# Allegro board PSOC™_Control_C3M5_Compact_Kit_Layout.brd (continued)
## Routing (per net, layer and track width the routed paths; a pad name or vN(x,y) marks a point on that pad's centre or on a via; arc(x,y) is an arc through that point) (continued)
XTAL1: length 8.3
  BOTTOM w0.152: Y1.1 24.86,19.77 24.64,19.55 22.44,19.55 22.25,19.74 C13.1 21.6,19.34 21.35,19.09 20.4,19.09 18.98,17.67 U2.29
XTAL2: length 3.7
  BOTTOM w0.152: R12.1 21.66,18.36 22.23,18.36 22.58,18.71 Y1.3 23.56,17.81 23.69,17.68 C14.1
N07345: length 2.6
  TOP w0.381: 6.1,8.62 J1.1 ; 8.15,7.52 8.22,7.59 FB1.1 9.82,7.59
N07349: length 4.4
  TOP w0.381: FB1.2 9.82,6.09 ; FB1.2 9.09,5.41 ; FB1.2 8.36,6.09 ; 11,6.22 D1.A 10.47,5.59 ; 9.68,4.6 C10.1 9.13,5.14
N08163: length 7.4
  TOP w0.381: v1(43.21,23.4) 43.33,23.27 v1(43.33,22.81) 43.64,22.51 43.64,21.77 v1(42.57,20.71)
  BOTTOM w0.381: L1.2 42.88,23.55 ; v1(42.57,20.71) 41.95,20.08 U5.1 ; 43.54,23.12 D2.A 44.07,23.76
N11111: length 2.5
  BOTTOM w0.229: R14.2 9.4,14.51 9.57,14.69 10.45,14.69 10.93,15.17 U2.3
N20632: length 15.1
  TOP w0.381: v1(39.9,19.79) 40.4,20.28 41.8,20.28 41.96,20.12 42.88,20.12 44.27,21.52 44.27,22.74 v1(44.93,23.4)
  BOTTOM w0.33: R4.1 45.69,24.14 45.94,23.89 46.34,23.89 46.35,23.89 47.78,23.89 R1.2
  BOTTOM w0.381: v1(39.9,19.79) 40.05,19.65 U5.3 ; C1.2 49.86,23.41 R1.2 ; v1(44.93,23.4) 44.93,24.16 45.31,24.54 R4.1
N32254: length 2.6
  BOTTOM w0.152: R12.2 20.22,18.34 19.05,17.17 U2.30
N37178: length 4
  TOP w0.203: U3.8 41.31,6.56 41.52,6.35 v1(41.53,6.35)
  BOTTOM w0.203: v1(41.53,6.35) 42.05,5.83 R18.2 43.41,5.83 43.42,5.83 43.92,5.83 C28.1
N38243: length 4.8
  TOP w0.292: U3.30 35,13.75 v1(34.9,13.64)
  BOTTOM w0.356: C25.1 37.93,13.6 37.64,13.9 35.15,13.9 v1(34.9,13.64)
N38502: length 40.2
  TOP w0.229: U3.13 47.33,8.17 ; 47.29,9.5 47.3,9.5 U3.15 ; U3.14 47.32,8.9 ; U3.12 47.26,7.57
  TOP w0.254: U3.20 47.21,18.58 ; U3.21 45.71,18.6
  TOP w0.381: U3.12 48.51,7.57 ; U3.15 48.51,9.5 ; U3.20 47.96,19 48.01,18.95 ; U3.14 48.51,8.9 ; U3.13 v1(48.51,8.17)
  TOP w0.457: v1(52.93,8.84) v1(52.93,9.48) 52.91,9.5 52.91,17.17 52.1,17.99 v1(50.98,17.99)
  BOTTOM w0.152: TIE1.1 47.85,11.92 48.31,11.46 R16.1
  BOTTOM w0.254: v1(49.43,8.18) 49.42,8.2 47.74,8.2
  BOTTOM w0.305: 47.74,8.2 47.01,7.46 47.01,5.08 46.5,4.57 45.64,4.57 45.21,4.14 41.07,4.14 40.09,5.12 R19.1
  BOTTOM w0.381: R16.1 49.12,10.04 ; R16.1 47.51,10.04 ; R16.1 48.31,8.46 ; v1(52.93,9.48) v1(52.93,8.84) 52.86,8.77 49.68,8.77 v1(49.66,8.75)
  vias: v1(49.43,10.57) v1(49.63,9.91) v1(49.64,9.33) v1(49.71,18.6) v1(49.71,17.99) v1(50.34,18.6) v1(50.34,17.99) v1(50.98,18.6)
N50220: length 8.3
  BOTTOM w0.152: R10.1 R8.1 7.21,19.06 7.5,19.06 7.68,19.23 9.5,19.23 10.57,18.17 10.57,17.56 10.95,17.17 U2.7
N86492: length 1.9
  TOP w0.152: v1(6.33,24.13) 6.05,24.41 D3.A
  BOTTOM w0.152: R7.2 6.25,24.21 v1(6.33,24.13)
N117783: length 7
  BOTTOM w0.152: R31.2 34.52,19.24 34.37,19.4 34.37,20.55 34.52,20.7 U6.3 37.03,20.7 C46.1 ; C46.1 38.28,20.67 R68.2 ; C46.1 R69.1
N117862: length 5.8
  BOTTOM w0.152: R33.2 33.91,19.24 34.06,19.4 34.06,20.55 33.91,20.7 U6.4 31.85,20.7 C50.1 30.25,21.08 R36.1
N117920: length 16.7
  TOP w0.152: R32.1 26.67,21.67 26.82,21.82 v1(27.3,21.82)
  BOTTOM w0.152: v1(27.3,21.82) 27.3,22.08 29.03,23.8 34.82,23.8 35.57,23.06 U6.1 34.66,22.6 34.12,22.06 C50.2 30.25,22.06 R36.2
N133373: length 2
  TOP w0.152: v1(14.73,24.54) 14.61,24.41 D7.K
  BOTTOM w0.152: v1(14.73,24.54) 14.96,24.31 R26.2
N133421: length 1.9
  TOP w0.152: D8.K v1(10.54,24.41)
  BOTTOM w0.152: v1(10.54,24.41) 10.46,24.33 R29.2
N143868: length 2.4
  TOP w0.152: R21.2 30.79,23.25 R20.2
N214953: length 2.4
  BOTTOM w0.152: R39.1 16.34,11.72 16.74,12.12 U2.39
N215126: length 3.3
  BOTTOM w0.152: U2.36 18.44,12.25 17.91,11.72 R40.1
N223602: length 7
  BOTTOM w0.152: R51.2 48.33,1.27 52.3,1.27 53.21,2.19 J3.9
N254765: length 19.1
  BOTTOM w0.152: R53.2 23.7,9.51 18.57,9.51 18.41,9.35 16.25,9.35 15.6,8.7 12.46,8.7 11.58,9.58 11.58,11.41 11.73,11.56 12.24,11.56 12.85,12.17 12.85,12.88 12.74,13 U2.47
N255191: length 2.1
  TOP w0.152: D9.A 5.4,22.93 v1(4.95,23.38)
  BOTTOM w0.152: R47.2 4.71,23.61 v1(4.95,23.38)
N338896: length 6.1
  TOP w0.152: D10.A 44.61,4.32 R63.2 43.16,4.75 42.77,5.14 41.86,5.14 40.66,6.33 U3.7
N367460: length 4
  BOTTOM w0.229: U2.4 10.54,15.67 10.19,15.32 8.86,15.32 R13.2
N371560: length 1.6
  TOP w0.152: R48.1 28.39,9.82 28.07,10.14 U1.10

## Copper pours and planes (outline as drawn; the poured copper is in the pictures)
15V_OUT on TOP: 36.73,10.01 35.56,10.01 35.33,9.78 35.33,8.84 35.59,8.59 36.86,8.59 36.93,8.67 36.93,9.81
15V_OUT on BOTTOM: 43.79,19.59 43.31,20.07 43.31,21.09 43.79,21.57 47.07,21.57 47.5,22 57.12,22 57.23,21.9 57.23,20.73 56.59,20.1 52.04,20.1 51.54,19.59
GND_EARTH on BOTTOM: 3.94,8.04 5.68,9.78 5.68,16.47 5.03,17.12 2.82,17.12 2.31,16.62 2.31,4.03 2.63,3.71 3.94,3.71 3.94,3.71
GND_SIGNAL on TOP: 0.76,24.73 0.95,25.09 1.33,25.23 53.72,25.24 57.57,25.24 57.81,25 57.81,23.55 57.66,23.4 53.87,23.4 53.72,23.25 53.72,12.22 52.63,12.22 52.63,8.74 53.72,8.74 53.72,0.76 1.27,0.76 0.91,0.91 0.76,1.27 0.76,6.18 2.26,6.18 2.26,19.82 0.76,19.82 ; 25 cut-outs
GND_SIGNAL on BOTTOM: 53.47,25.24 57.29,25.24 57.81,24.72 57.81,23.25 57.35,22.79 54.71,22.79 54.64,22.86 53.64,22.86 53.47,22.69 53.47,19.92 52.15,19.92 51.68,19.45 49.64,19.45 49.23,19.03 49.23,17.07 48.67,17.07 48.67,11.87 48.72,11.87 48.72,11.46 49.15,11.46 49.15,11.87 53.47,11.87 53.47,11.76 50.7,11.76 50.11,11.18 50.11,8.56 50.42,8.26 50.22,8.26 50.22,7.68 51.28,7.68 51.28,2.37 52.15,2.37 52.15,7.68 53.06,7.68 53.06,2.19 53.47,2.19 53.47,0.76 1.27,0.76 0.91,0.91 0.76,1.27 0.76,6.18 2.26,6.18 2.26,19.82 0.76,19.82 0.76,24.73 0.95,25.09 1.33,25.23 ; 13 cut-outs
VBUS on TOP: 10.26,7.32 10.44,7.14 13.72,7.14 13.89,6.96 15.21,6.96 15.39,7.14 15.39,8.36 14.33,9.43 10.54,9.43 10.26,9.15
VBUS on BOTTOM: 40.18,24.57 39.22,24.57 38.73,24.08 38.73,20.76 39.01,20.48 41.99,20.48 42.52,21.01 42.52,21.7 42.11,22.1 40.82,22.1 40.41,22.51 40.41,24.34
VBUS on BOTTOM: 17.35,4.98 15.62,4.98 15.37,5.24 15.37,6.43 16.48,7.55 17.86,7.55 17.96,7.65 17.96,8.11 17.78,8.28 14.2,8.28 13.59,7.68 13.59,4.22 14.22,3.59 17.32,3.59 17.75,4.02 17.75,4.58
VCC_3V3 on TOP: 13.91,3.16 11.57,3.16 11.28,2.87 11.28,1.03 11.51,0.79 14.7,0.79 14.85,0.94 14.85,2.22
VCC_3V3 on BOTTOM: 30.78,6.05 30.99,5.85 30.99,3.79 30.35,3.15 26.87,3.15 26.29,2.57 19.05,2.57 18.61,2.13 18.62,2.11 18.62,0.97 18.44,0.79 11.51,0.79 11.28,1.03 11.28,2.93 11.56,3.22 13.42,3.22 13.99,2.65 14.96,2.65 15.82,3.51 21.67,3.51 22.91,4.75 22.91,5.77 23.19,6.05
IPM_V+ on TOP (solid shape): 43.86,15.8 43.36,15.3 36.12,15.3 36.12,18.7 43.86,18.7
IPM_V+ on BOTTOM: 37.77,16.87 37.36,16.46 37.36,15.37 37.8,14.94 44.53,14.94 44.65,15.07 44.65,16.64 44.42,16.87
U on TOP (solid shape): 46.15,7.44 43.13,7.44 43.13,9.84 46.15,9.84
U on TOP: 43.61,7.19 43.43,7.01 43.43,6.33 43.97,5.8 50.98,5.8 52.32,7.14 52.32,10.82 51.82,11.33 50.42,11.33 50.34,11.26 50.34,7.6 49.76,7.01 46.96,7.01 46.79,7.19
V on TOP (solid shape): 47.36,10.84 43.87,10.84 43.87,13.24 47.36,13.24
V on TOP: 51.92,13.77 47.88,13.77 47.27,13.16 47.27,11.23 47.42,11.08 49.68,11.08 50.16,11.56 51.82,11.56 52.07,11.82 52.07,13.62
VBACKUP on TOP: 31.01,11.26 26.98,11.26 26.24,10.51 26.24,9.22 25.79,8.78 25.79,7.98 26.06,7.71 30.33,7.71 30.7,7.35 32.33,7.35 32.6,7.61 32.6,9.66
W on TOP (solid shape): 47.41,14.23 44.86,14.23 44.86,17.44 47.41,17.44
W on TOP: 51.41,17.2 47.32,17.2 47.27,17.15 47.27,14.43 47.37,14.33 51.64,14.33 52.07,14.76 52.07,16.54
N07345 on TOP: 5.31,10.06 9.53,10.06 10.01,9.58 10.01,7.35 9.83,7.17 5.49,7.17 5.31,7.35
N07349 on TOP: 11.25,6.61 7.65,6.61 7.39,6.35 7.39,5.19 7.75,4.83 8.76,4.83 8.76,4.35 8.89,4.22 9.65,4.22 9.65,4.32 10.16,4.83 11.4,4.83 11.51,4.93 11.51,6.35
N08163 on BOTTOM: 43.99,24.64 41.96,24.64 41.73,24.41 41.73,22.81 42.01,22.53 44.09,22.53 44.35,22.79 44.35,24.29
N38502 on TOP: 47.83,19.71 51.87,19.71 52.12,19.46 52.12,16.49 51.1,17.51 48.03,17.51 47.62,17.91 47.62,19.51
N38502 on TOP: 49.61,10.8 48.08,10.8 47.37,10.09 47.37,7.6 47.62,7.35 49.53,7.35 49.96,7.78 49.96,10.44
N38502 on BOTTOM: 49.45,19.18 49.28,19 49.28,17.86 49.45,17.68 51.03,17.68 51.23,17.89 51.23,19.03 51.08,19.18
N38502 on BOTTOM: 47.09,11.1 47.09,8.16 47.32,7.93 49.66,7.93 49.96,8.23 49.96,9.94 49.81,10.09 49.81,11 49.43,11.38 47.37,11.38

Small or netless copper shapes (teardrops, artwork), in the pictures only: 3 on TOP

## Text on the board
BOTTOM: BOTTOM SIDE
Ref Des/Assembly Bottom: ASSEMBLY BOTTOM
Board Geometry/Soldermask Bottom: SOLDERMASK BOTTOM
Ref Des/Silkscreen Bottom: 1 | DEBUGGER | GND | REV02 | 600-60706-01 | SILKSCREEN BOTTOM
TOP: TOP SIDE
Ref Des/Assembly Top: ASSEMBLY TOP
Board Geometry/Soldermask Top: SOLDERMASK TOP
Ref Des/Silkscreen Top: DEBUG | POWER | J1 | USER LEDs | VCC.3V3 | GND | VBUS | PSOC.C3 | GK.IPM | POT | V.TRIP | IPM.V | 15V.OUT | USER BTN | XRES | KIT PSC3M5 2GO | SILKSCREEN TOP
PASTEMASK_TOP: SOLDERPASTE TOP
PAGE_OUTLINE: SOLDERPASTE BOTTOM
User.6: GOLDMASK TOP
User.7: GOLDMASK BOTTOM
User.21: 10. NET TIE: | A SEPERATE ELECTRICAL LAYER "SHORT_BOTTOM.ART" IS INCLUDED IN THE ARTWORK PACKAGE | THIS LAYER WILL ELECTRICALLY SHORT FEW DISCRETE IN BOTTOM LAYER, FOR REFERENCE | PLEASE CHECK DETAIL3.ART LAYER
User.45: TOTAL 2no's SHORT NET ON BOARD | SHORT NET | DETAIL3 | FIGURE | FINISHED_SIZE | 7.87 | 25.0 | 39.37 | 40.16 | 74.8 | 55.12 | 56.0 | 157.48 | DRILLED_SIZE | - | DRILL CHART: TOP to BOTTOM | ALL UNITS ARE IN MILS | FINISHED_TOL | +3.0/-3.0 | +2.0/-2.0 | DRILLED_TOL | PLATED | NON-PLATED | QTY | 298 | 3 | 5 | 8 | 2 | 1 | 323 | TOTAL HOLES:
